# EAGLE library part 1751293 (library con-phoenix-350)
MKDS 1/ 7-3,5 Printklemme Nennstrom: 10 A Bemessungsspannung: 160 V Raster: 3,5 mm Polzahl: 7 Montageart: Löten Anschlussart: Schraubanschluss Anschlussrichtung vom Leiter zur Platine: 0° Source: http://eshop.phoenixcontact.com .. 1751293.pdf
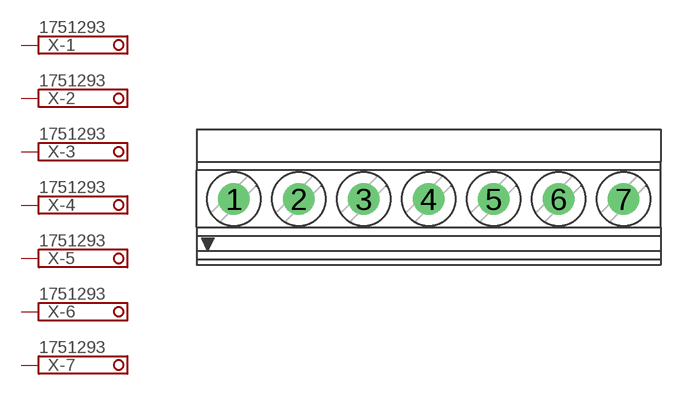
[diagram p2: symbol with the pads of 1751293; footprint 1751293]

Designator prefix X; gates -1=SCHRAUBKLEMME -2=SCHRAUBKLEMME -3=SCHRAUBKLEMME -4=SCHRAUBKLEMME -5=SCHRAUBKLEMME -6=SCHRAUBKLEMME -7=SCHRAUBKLEMME

## 1751293 (OC_FARNELL: unknown; OC_NEWARK: unknown)  [1751293]
1  -1:K  pas
2  -2:K  pas
3  -3:K  pas
4  -4:K  pas
5  -5:K  pas
6  -6:K  pas
7  -7:K  pas

## Footprint 1751293 (pad centres in mm)
MKDS 1/ 7-3,5 Printklemme Nennstrom: 10 A Bemessungsspannung: 160 V Raster: 3,5 mm Polzahl: 7 Montageart: Löten Anschlussart: Schraubanschluss Anschlussrichtung vom Leiter zur Platine: 0° Source: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
drill 1.1 pad 1.7 round: 1 -10.5,-0.1; 2 -7,-0.1; 3 -3.5,-0.1; 4 0,-0.1; 5 3.5,-0.1; 6 7,-0.1; 7 10.5,-0.1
